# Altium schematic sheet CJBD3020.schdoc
size 127 x 101 mm
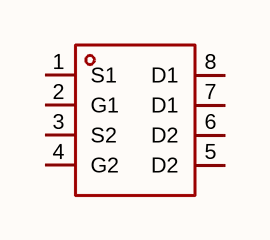
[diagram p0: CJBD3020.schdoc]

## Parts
Q?  cjbd3020  [PDFNWB-8_L3.0-W3.0-P0.65-LS3.3-BL]  (value not drawn)

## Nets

Not connected (* = marked no-connect by the designer): Q? 1(S1) 2(G1) 3(S2) 4(G2) 5(D2) 6(D2) 7(D1) 8(D1)

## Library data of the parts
Q? = cjbd3020: 数量:2个N沟道;漏源电压(Vdss):30V;连续漏极电流(Id):20A;导通电阻(RDS(on)):9.5mΩ@10V;耗散功率(Pd):1.5W;阈值电压(Vgs(th)):1V;; Manufacturer: CJ(江苏长电/长晶); AddInBom: yes; ModelId: d559774c40b44b358e36b10995f2dcb2; ModelTransform: 122.047,129.921,0,0,0,0,0,0,0; Number: 2个N沟道; Drain to Source Voltage: 30V; Current - Continuous Drain(Id): 20A; Pd - Power Dissipation: 1.5W; Gate Threshold Voltage (Vgs(th)): 1V; Gate Charge(Qg): 14nC@10V; Input Capacitance(Ciss): 823pF; Reverse Transfer Capacitance (Crss@Vds): 100pF; Type: N沟道; Output Capacitance(Coss): 138pF; Vgs: ±20V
